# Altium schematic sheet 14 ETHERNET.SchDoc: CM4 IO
size 297 x 209 mm; Page Create Date: March  8, 1995; Page Number: 14; Page Size: A4; Comment: radxa_1010; Page Count: 19; RevCode: V1.10; Doc: 14 ETHERNET; DsnPath: D:\WMS\黄工\[RC126]CM4_IO_V1.10\[RC126]_V1.10\CM4 IO_V1.10.DSN; SchematicName: CM4 IO V1.10; PageName: 14 ETHERNET; PageSize: A4; TopSchematic: True
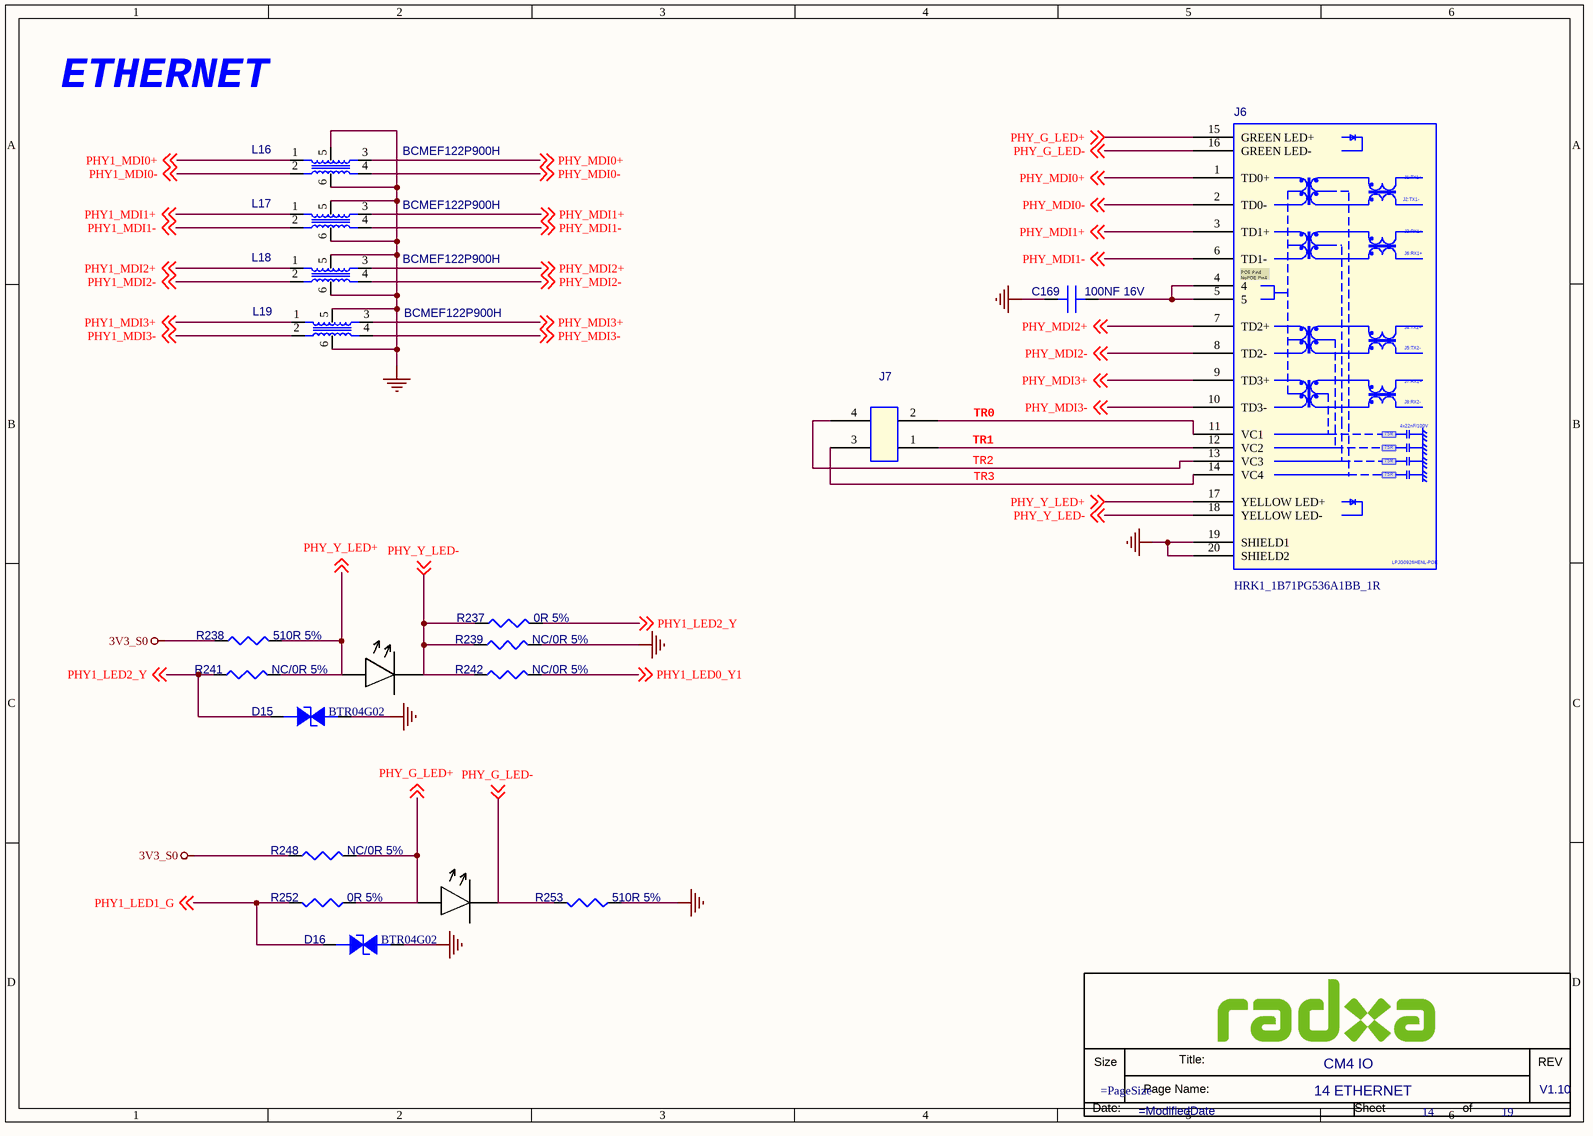
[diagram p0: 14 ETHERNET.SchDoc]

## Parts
*  Doc: 14 ETHERNET  RevCode: V1.10  Title: CM4 IO  Page Number: 14  Page Count: 19  (hidden comment: radxa_1010)  (graphical)
C169  100NF 16V  [C0201]
D15  BTR04G02  [DFN1006-2L]
D16  BTR04G02  [DFN1006-2L]
J6  HRK1_1B71PG536A1BB_1R  [RJ45_LED_TH22_LIE]
J7  (no value)  [CONM_TH2X2_2D54_STA]
L16  BCMEF122P900H  [CML_SM6_0D6_1D5]
L17  BCMEF122P900H  [CML_SM6_0D6_1D5]
L18  BCMEF122P900H  [CML_SM6_0D6_1D5]
L19  BCMEF122P900H  [CML_SM6_0D6_1D5]
R237  0R 5%  [R0402]
R238  510R 5%  [R0402]
R239  NC/0R 5%  [R0402]
R241  NC/0R 5%  [R0402]
R242  NC/0R 5%  [R0402]
R248  NC/0R 5%  [R0402]
R252  0R 5%  [R0402]
R253  510R 5%  [R0402]

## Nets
3V3_S0: R238.1 R248.2
GND: C169.1(A) D15.2(CATHODE) D16.2(CATHODE) J6.19(SHIELD1) J6.20(SHIELD2) L16.5 L16.6 L17.5 L17.6 L18.5 L18.6 L19.5 L19.6 R239.1 R253.2
PHY1_LED0_Y1: R242.2 ; off-sheet PHY1_LED0_Y1
PHY1_LED1_G: D16.1(ANODE) R252.1 ; off-sheet PHY1_LED1_G
PHY1_LED2_Y: D15.1(ANODE) R237.2 R241.1 ; off-sheet PHY1_LED2_Y
PHY1_MDI0+: L16.1(R1) ; off-sheet PHY1_MDI0+
PHY1_MDI0-: L16.2(R2) ; off-sheet PHY1_MDI0-
PHY1_MDI1+: L17.1(R1) ; off-sheet PHY1_MDI1+
PHY1_MDI1-: L17.2(R2) ; off-sheet PHY1_MDI1-
PHY1_MDI2+: L18.1(R1) ; off-sheet PHY1_MDI2+
PHY1_MDI2-: L18.2(R2) ; off-sheet PHY1_MDI2-
PHY1_MDI3+: L19.1(R1) ; off-sheet PHY1_MDI3+
PHY1_MDI3-: L19.2(R2) ; off-sheet PHY1_MDI3-
PHY_G_LED+: J6.15(GREEN_LED+) R248.1 R252.2 ; off-sheet PHY_G_LED+
PHY_G_LED-: J6.16(GREEN_LED-) R253.1 ; off-sheet PHY_G_LED-
PHY_MDI0+: J6.1(TD0+) L16.3(R4) ; off-sheet PHY_MDI0+
PHY_MDI0-: J6.2(TD0-) L16.4(R3) ; off-sheet PHY_MDI0-
PHY_MDI1+: J6.3(TD1+) L17.3(R4) ; off-sheet PHY_MDI1+
PHY_MDI1-: J6.6(TD1-) L17.4(R3) ; off-sheet PHY_MDI1-
PHY_MDI2+: J6.7(TD2+) L18.3(R4) ; off-sheet PHY_MDI2+
PHY_MDI2-: J6.8(TD2-) L18.4(R3) ; off-sheet PHY_MDI2-
PHY_MDI3+: J6.9(TD3+) L19.3(R4) ; off-sheet PHY_MDI3+
PHY_MDI3-: J6.10(TD3-) L19.4(R3) ; off-sheet PHY_MDI3-
PHY_Y_LED+: J6.17(YELLOW_LED+) R238.2 R241.2 ; off-sheet PHY_Y_LED+
PHY_Y_LED-: J6.18(YELLOW_LED-) R237.1 R239.2 R242.1 ; off-sheet PHY_Y_LED-
TR0: J6.11(VC1) J7.2
TR1: J6.12(VC2) J7.1
TR2: J6.13(VC3) J7.4
TR3: J6.14(VC4) J7.3
NetC169_2: C169.2(B) J6.4 J6.5

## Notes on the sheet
- ETHERNET

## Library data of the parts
C169 = C: SMD  0201  100NF  16V  X5R  ±20%  ROHS; PARTS: 1; Part Reference: C169; Part Number: A1C01.00099; OriginalSymbolOrigin: (0,30); PKG_TYPE: CAP2-100-250; LEVEL: STD; PINSWAP: (A,B); Preferred: 6715f349cd0bc5
D15 = ESD: SMD  编带  0402  BTR04G02  B-tron  ROHS; Part Reference: D15; Part Number: A1D02.00002; Parameter: ESD-台舟 ESD5341N-封装 esd0402; ID: DE-E0004; Temp Coeff: -50℃ ~ +125℃; PCB Footprint: ESD_D0402
D16 = ESD: SMD  编带  0402  BTR04G02  B-tron  ROHS; Part Reference: D16; Part Number: A1D02.00002; Parameter: ESD-台舟 ESD5341N-封装 esd0402; ID: DE-E0004; Temp Coeff: -50℃ ~ +125℃; PCB Footprint: ESD_D0402
J6 = LPJG0926HENL: DIP  母座  千兆网  带POE功能  18PIN  21.5*16*13.7mm  HRK1-1B71PG536A1BB-1R  镀镍  带指示灯  无弹片  左绿右黄  ROHS; Part Reference: J6; Part Number: A1J03.00012; Parameter: 连接器-带POE功能的集成变压器RJ45
J7 = CON_2X2: DIP  排针座  2*2PIN  180度  2.54mm脚距  中间朔高2.5mm  针长一端6.1mm  另一端3.0mm  黑色  PH2.54 2*02P L=11.6/3.0  S/T  国意英  ROHS; Part Reference: J7; Part Number: A1J01.00011; Temp Coeff: -40℃ to +105℃; Preferred: 6715f349cd0bc5
L16 = BCMEF122P900H: SMD  BCMEF122P900H  90R  6PIN  带ESD  ±25%  B-tron  ROHS; Part Number: A1L03.00001; Part Reference: L16; Temp Coeff: -40℃ to +105℃; Preferred: 6715f349cd0bc5; PCB Footprint: CML_SM6_0D55_1
L17 = BCMEF122P900H: SMD  BCMEF122P900H  90R  6PIN  带ESD  ±25%  B-tron  ROHS; Part Number: A1L03.00001; Part Reference: L17; Temp Coeff: -40℃ to +105℃; Preferred: 6715f349cd0bc5; PCB Footprint: CML_SM6_0D55_1
L18 = BCMEF122P900H: SMD  BCMEF122P900H  90R  6PIN  带ESD  ±25%  B-tron  ROHS; Part Number: A1L03.00001; Part Reference: L18; Temp Coeff: -40℃ to +105℃; Preferred: 6715f349cd0bc5; PCB Footprint: CML_SM6_0D55_1
L19 = BCMEF122P900H: SMD  BCMEF122P900H  90R  6PIN  带ESD  ±25%  B-tron  ROHS; Part Number: A1L03.00001; Part Reference: L19; Temp Coeff: -40℃ to +105℃; Preferred: 6715f349cd0bc5; PCB Footprint: CML_SM6_0D55_1
R237 = R: SMD  0201  0R  1/20W  ±5%  ROHS; Part Reference: R237; Part Number: A1R01.00027; PCB Footprint: R0201; Temp Coeff: －55℃ ~ ＋125℃
R238 = R: SMD  0201  510R  1/20W  ±5%  ROHS; Part Reference: R238; Part Number: A1R01.00019; PCB Footprint: R0201
R239 = R: SMD  0201  0R  1/20W  ±5%  ROHS; Part Reference: R239; Part Number: A1R01.00027; PCB Footprint: R0201; Temp Coeff: －55℃ ~ ＋125℃
R241 = R: SMD  0201  0R  1/20W  ±5%  ROHS; Part Reference: R241; Part Number: A1R01.00027; PCB Footprint: R0201; Temp Coeff: －55℃ ~ ＋125℃
R242 = R: SMD  0201  0R  1/20W  ±5%  ROHS; Part Reference: R242; Part Number: A1R01.00027; PCB Footprint: R0201; Temp Coeff: －55℃ ~ ＋125℃
R248 = R: SMD  0201  0R  1/20W  ±5%  ROHS; Part Reference: R248; Part Number: A1R01.00027; PCB Footprint: R0201; Temp Coeff: －55℃ ~ ＋125℃
R252 = R: SMD  0201  0R  1/20W  ±5%  ROHS; Part Reference: R252; Part Number: A1R01.00027; PCB Footprint: R0201; Temp Coeff: －55℃ ~ ＋125℃
R253 = R: SMD  0201  510R  1/20W  ±5%  ROHS; Part Reference: R253; Part Number: A1R01.00019; PCB Footprint: R0201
